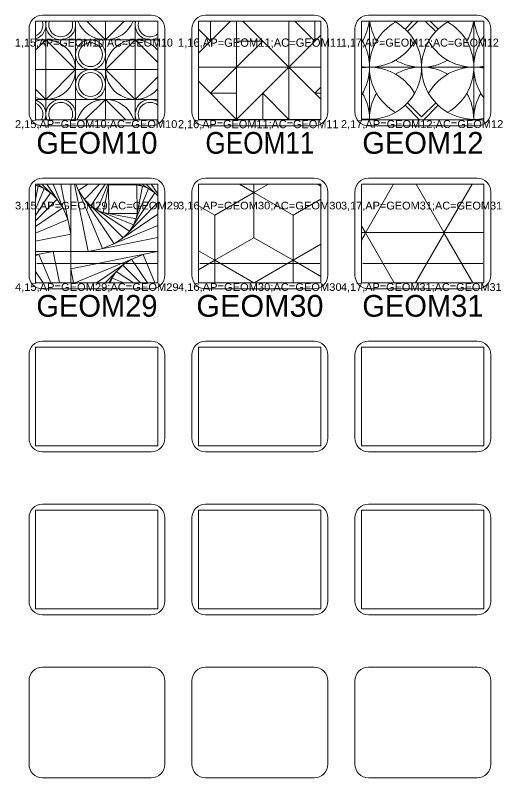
# Model space of a CAD drawing. Extents: x 95935 to 95946.4, y 95971.2 to 95974.7.
# Drawn here: x 95943.435 to 95945.23, y 95971.925 to 95974.732 of the extents above; entities that cross this region are included whole.
import ezdxf
from ezdxf.enums import TextEntityAlignment as Align

# ---------------------------------------------------------------- set-up
doc = ezdxf.new("R2010")
doc.units = 0
doc.header["$LTSCALE"] = 0.032
for name, color, linetype, lineweight in [('1', 7, 'Continuous', 13), ('2', 7, 'Continuous', 13), ('25', 7, 'Continuous', 13), ('6', 7, 'Continuous', 13), ('63', 7, 'Continuous', 13)]:
    doc.layers.add(name, color=color, linetype=linetype, lineweight=lineweight)
doc.layers.add('20', color=7, linetype='Continuous')

msp = doc.modelspace()

# ---------------------------------------------------------------- linework, layer by layer
at = {"layer": '1'}
for p, q in [((95943.5357, 95974.7318), (95943.9357, 95974.7318)), ((95944.1357, 95974.7318), (95944.5357, 95974.7318)), ((95944.7357, 95974.7318), (95945.1357, 95974.7318)), ((95943.4857, 95974.3747), (95943.4857, 95974.6818)), ((95943.9857, 95974.6818), (95943.9857, 95974.3747)), ((95944.0857, 95974.3747), (95944.0857, 95974.6818)), ((95944.5857, 95974.6818), (95944.5857, 95974.3747)), ((95944.6857, 95974.3747), (95944.6857, 95974.6818)), ((95945.1857, 95974.6818), (95945.1857, 95974.3747)), ((95943.9357, 95974.3247), (95943.5357, 95974.3247)), ((95944.5357, 95974.3247), (95944.1357, 95974.3247)), ((95945.1357, 95974.3247), (95944.7357, 95974.3247)), ((95943.5357, 95974.1318), (95943.9357, 95974.1318)), ((95944.1357, 95974.1318), (95944.5357, 95974.1318)), ((95944.7357, 95974.1318), (95945.1357, 95974.1318)), ((95943.4857, 95973.7747), (95943.4857, 95974.0818)), ((95943.9857, 95974.0818), (95943.9857, 95973.7747)), ((95944.0857, 95973.7747), (95944.0857, 95974.0818)), ((95944.5857, 95974.0818), (95944.5857, 95973.7747)), ((95944.6857, 95973.7747), (95944.6857, 95974.0818)), ((95945.1857, 95974.0818), (95945.1857, 95973.7747)), ((95943.9357, 95973.7247), (95943.5357, 95973.7247)), ((95944.5357, 95973.7247), (95944.1357, 95973.7247)), ((95945.1357, 95973.7247), (95944.7357, 95973.7247)), ((95943.5357, 95973.5318), (95943.9357, 95973.5318)), ((95944.1357, 95973.5318), (95944.5357, 95973.5318)), ((95944.7357, 95973.5318), (95945.1357, 95973.5318)), ((95943.4857, 95973.1747), (95943.4857, 95973.4818)), ((95943.9857, 95973.4818), (95943.9857, 95973.1747)), ((95944.0857, 95973.1747), (95944.0857, 95973.4818)), ((95944.5857, 95973.4818), (95944.5857, 95973.1747)), ((95944.6857, 95973.1747), (95944.6857, 95973.4818)), ((95945.1857, 95973.4818), (95945.1857, 95973.1747)), ((95943.9357, 95973.1247), (95943.5357, 95973.1247)), ((95944.5357, 95973.1247), (95944.1357, 95973.1247)), ((95945.1357, 95973.1247), (95944.7357, 95973.1247)), ((95943.5357, 95972.9318), (95943.9357, 95972.9318)), ((95944.1357, 95972.9318), (95944.5357, 95972.9318)), ((95944.7357, 95972.9318), (95945.1357, 95972.9318)), ((95943.4857, 95972.5747), (95943.4857, 95972.8818)), ((95943.9857, 95972.8818), (95943.9857, 95972.5747)), ((95944.0857, 95972.5747), (95944.0857, 95972.8818)), ((95944.5857, 95972.8818), (95944.5857, 95972.5747)), ((95944.6857, 95972.5747), (95944.6857, 95972.8818)), ((95945.1857, 95972.8818), (95945.1857, 95972.5747)), ((95943.9357, 95972.5247), (95943.5357, 95972.5247)), ((95944.5357, 95972.5247), (95944.1357, 95972.5247)), ((95945.1357, 95972.5247), (95944.7357, 95972.5247)), ((95943.5357, 95972.3318), (95943.9357, 95972.3318)), ((95944.1357, 95972.3318), (95944.5357, 95972.3318)), ((95944.7357, 95972.3318), (95945.1357, 95972.3318)), ((95944.7357, 95972.3318), (95945.1357, 95972.3318)), ((95943.4857, 95971.9747), (95943.4857, 95972.2818)), ((95943.9857, 95972.2818), (95943.9857, 95971.9747)), ((95944.0857, 95971.9747), (95944.0857, 95972.2818)), ((95944.5857, 95972.2818), (95944.5857, 95971.9747)), ((95944.6857, 95971.9747), (95944.6857, 95972.2818)), ((95944.6857, 95971.9747), (95944.6857, 95972.2818)), ((95945.1857, 95972.2818), (95945.1857, 95971.9747)), ((95945.1857, 95972.2818), (95945.1857, 95971.9747)), ((95943.9357, 95971.9247), (95943.5357, 95971.9247)), ((95944.5357, 95971.9247), (95944.1357, 95971.9247)), ((95945.1357, 95971.9247), (95944.7357, 95971.9247)), ((95945.1357, 95971.9247), (95944.7357, 95971.9247))]:
    msp.add_line(p, q, dxfattribs=at)
for centre, start, end in [((95943.5357, 95974.6818), 90, 180), ((95943.9357, 95974.6818), 0, 90), ((95944.1357, 95974.6818), 90, 180), ((95944.5357, 95974.6818), 0, 90), ((95944.7357, 95974.6818), 90, 180), ((95945.1357, 95974.6818), 0, 90), ((95943.5357, 95974.3747), 180, 270), ((95943.9357, 95974.3747), 270, 0), ((95944.1357, 95974.3747), 180, 270), ((95944.5357, 95974.3747), 270, 0), ((95944.7357, 95974.3747), 180, 270), ((95945.1357, 95974.3747), 270, 0), ((95943.5357, 95974.0818), 90, 180), ((95943.9357, 95974.0818), 0, 90), ((95944.1357, 95974.0818), 90, 180), ((95944.5357, 95974.0818), 0, 90), ((95944.7357, 95974.0818), 90, 180), ((95945.1357, 95974.0818), 0, 90), ((95943.5357, 95973.7747), 180, 270), ((95943.9357, 95973.7747), 270, 0), ((95944.1357, 95973.7747), 180, 270), ((95944.5357, 95973.7747), 270, 0), ((95944.7357, 95973.7747), 180, 270), ((95945.1357, 95973.7747), 270, 0), ((95943.5357, 95973.4818), 90, 180), ((95943.9357, 95973.4818), 0, 90), ((95944.1357, 95973.4818), 90, 180), ((95944.5357, 95973.4818), 0, 90), ((95944.7357, 95973.4818), 90, 180), ((95945.1357, 95973.4818), 0, 90), ((95943.5357, 95973.1747), 180, 270), ((95943.9357, 95973.1747), 270, 0), ((95944.1357, 95973.1747), 180, 270), ((95944.5357, 95973.1747), 270, 0), ((95944.7357, 95973.1747), 180, 270), ((95945.1357, 95973.1747), 270, 0), ((95943.5357, 95972.8818), 90, 180), ((95943.9357, 95972.8818), 0, 90), ((95944.1357, 95972.8818), 90, 180), ((95944.5357, 95972.8818), 0, 90), ((95944.7357, 95972.8818), 90, 180), ((95945.1357, 95972.8818), 0, 90), ((95943.5357, 95972.5747), 180, 270), ((95943.9357, 95972.5747), 270, 0), ((95944.1357, 95972.5747), 180, 270), ((95944.5357, 95972.5747), 270, 0), ((95944.7357, 95972.5747), 180, 270), ((95945.1357, 95972.5747), 270, 0), ((95943.5357, 95972.2818), 90, 180), ((95943.9357, 95972.2818), 0, 90), ((95944.1357, 95972.2818), 90, 180), ((95944.5357, 95972.2818), 0, 90), ((95944.7357, 95972.2818), 90, 180), ((95944.7357, 95972.2818), 90, 180), ((95945.1357, 95972.2818), 0, 90), ((95945.1357, 95972.2818), 0, 90), ((95943.5357, 95971.9747), 180, 270), ((95943.9357, 95971.9747), 270, 0), ((95944.1357, 95971.9747), 180, 270), ((95944.5357, 95971.9747), 270, 0), ((95944.7357, 95971.9747), 180, 270), ((95944.7357, 95971.9747), 180, 270), ((95945.1357, 95971.9747), 270, 0), ((95945.1357, 95971.9747), 270, 0)]:
    msp.add_arc(centre, 0.05, start, end, dxfattribs=at)
at = {"layer": '2'}
for points in [[(95943.9601, 95974.7099), (95943.5097, 95974.7099), (95943.5097, 95974.3468), (95943.9601, 95974.3468)], [(95944.5601, 95974.7099), (95944.1097, 95974.7099), (95944.1097, 95974.3468), (95944.5601, 95974.3468)], [(95945.1601, 95974.7099), (95944.7097, 95974.7099), (95944.7097, 95974.3468), (95945.1601, 95974.3468)], [(95943.9601, 95974.1099), (95943.5097, 95974.1099), (95943.5097, 95973.7468), (95943.9601, 95973.7468)], [(95944.5601, 95974.1099), (95944.1097, 95974.1099), (95944.1097, 95973.7468), (95944.5601, 95973.7468)], [(95945.1601, 95974.1099), (95944.7097, 95974.1099), (95944.7097, 95973.7468), (95945.1601, 95973.7468)], [(95943.9601, 95973.5099), (95943.5097, 95973.5099), (95943.5097, 95973.1468), (95943.9601, 95973.1468)], [(95944.5601, 95973.5099), (95944.1097, 95973.5099), (95944.1097, 95973.1468), (95944.5601, 95973.1468)], [(95945.1601, 95973.5099), (95944.7097, 95973.5099), (95944.7097, 95973.1468), (95945.1601, 95973.1468)], [(95943.9601, 95972.9099), (95943.5097, 95972.9099), (95943.5097, 95972.5468), (95943.9601, 95972.5468)], [(95944.5601, 95972.9099), (95944.1097, 95972.9099), (95944.1097, 95972.5468), (95944.5601, 95972.5468)], [(95945.1601, 95972.9099), (95944.7097, 95972.9099), (95944.7097, 95972.5468), (95945.1601, 95972.5468)]]:
    msp.add_lwpolyline(points, close=True, dxfattribs=at)
at = {"layer": '25'}
for p, q in [((95943.9569, 95973.8178), (95943.5141, 95973.8178)), ((95944.5569, 95973.8178), (95944.1141, 95973.8178)), ((95945.1569, 95973.8178), (95944.7141, 95973.8178))]:
    msp.add_line(p, q, dxfattribs=at)
at = {"layer": '6'}
for p, q in [((95943.5477, 95974.7099), (95943.5477, 95974.3468)), ((95943.6574, 95974.7099), (95943.6574, 95974.3468)), ((95943.6987, 95974.7099), (95943.7671, 95974.6415)), ((95943.7671, 95974.7099), (95943.7671, 95974.3468)), ((95943.7671, 95974.6415), (95943.8355, 95974.7099)), ((95943.8768, 95974.7099), (95943.8768, 95974.3468)), ((95944.1097, 95974.5922), (95944.2274, 95974.7099)), ((95944.2501, 95974.7099), (95944.2501, 95974.3468)), ((95944.2728, 95974.7099), (95944.5601, 95974.4226)), ((95944.4421, 95974.7099), (95944.4421, 95974.3468)), ((95944.7391, 95974.7099), (95944.7391, 95974.3468)), ((95944.8993, 95974.7099), (95944.8703, 95974.6808)), ((95944.9175, 95974.7099), (95944.8793, 95974.6718)), ((95944.9447, 95974.7099), (95944.9829, 95974.6718)), ((95944.9629, 95974.7099), (95944.9919, 95974.6808)), ((95945.1231, 95974.7099), (95945.1231, 95974.3468)), ((95943.5097, 95974.6415), (95943.9601, 95974.6415)), ((95944.2501, 95974.3486), (95944.5601, 95974.6586)), ((95943.5097, 95974.5318), (95943.9601, 95974.5318)), ((95944.1097, 95974.5406), (95944.5601, 95974.5406)), ((95944.7097, 95974.5406), (95945.1601, 95974.5406)), ((95943.8768, 95974.4221), (95943.9601, 95974.5054)), ((95944.1097, 95974.489), (95944.2501, 95974.3486)), ((95943.5097, 95974.4601), (95943.5477, 95974.4221)), ((95943.5097, 95974.4221), (95943.9601, 95974.4221)), ((95944.922, 95974.3486), (95944.8703, 95974.4004)), ((95944.9311, 95974.3577), (95944.8793, 95974.4094)), ((95944.9311, 95974.3577), (95944.9829, 95974.4094)), ((95944.9402, 95974.3486), (95944.9919, 95974.4004)), ((95944.1097, 95974.3486), (95944.5601, 95974.3486)), ((95944.1541, 95974.3468), (95944.1541, 95974.3486)), ((95944.2483, 95974.3468), (95944.2501, 95974.3486)), ((95944.2501, 95974.3486), (95944.2519, 95974.3468)), ((95944.4421, 95974.3486), (95944.4439, 95974.3468)), ((95944.5381, 95974.3468), (95944.5381, 95974.3486)), ((95944.922, 95974.3486), (95944.9202, 95974.3468)), ((95944.9402, 95974.3486), (95944.942, 95974.3468)), ((95943.6392, 95974.1099), (95943.6392, 95973.7468)), ((95943.6537, 95974.1099), (95943.7032, 95973.8623)), ((95943.6579, 95974.1099), (95943.7565, 95973.873)), ((95943.7027, 95974.1099), (95943.6676, 95974.0863)), ((95943.7453, 95974.1099), (95943.6896, 95974.0537)), ((95943.7659, 95974.1099), (95943.7133, 95974.0302)), ((95943.7758, 95974.1099), (95943.7369, 95974.0146)), ((95943.7793, 95974.1099), (95943.7593, 95974.0055)), ((95943.9031, 95974.1031), (95943.8676, 95974.1099)), ((95943.9254, 95974.094), (95943.8863, 95974.1099)), ((95943.9491, 95974.0784), (95943.9014, 95974.1099)), ((95943.9601, 95974.0675), (95943.9173, 95974.1099)), ((95943.9601, 95974.0739), (95943.9359, 95974.1099)), ((95943.9601, 95974.1053), (95943.9582, 95974.1099)), ((95944.2603, 95974.1099), (95944.3138, 95974.079)), ((95944.3138, 95974.079), (95944.3138, 95974.1099)), ((95944.3673, 95974.1099), (95944.3138, 95974.079)), ((95944.5483, 95974.1099), (95944.5601, 95974.1031)), ((95944.7239, 95973.9303), (95944.8276, 95974.1099)), ((95944.9108, 95974.1099), (95945.0127, 95973.9333)), ((95945.0132, 95973.9303), (95945.1169, 95974.1099)), ((95943.6676, 95974.0863), (95943.7992, 95973.8907)), ((95943.8553, 95973.9364), (95943.9491, 95974.0784)), ((95943.8709, 95973.96), (95943.9254, 95974.094)), ((95943.88, 95973.9824), (95943.9031, 95974.1031)), ((95944.1698, 95973.9959), (95944.3138, 95974.079)), ((95944.3138, 95974.079), (95944.3138, 95973.9127)), ((95944.4578, 95973.9959), (95944.3138, 95974.079)), ((95943.6896, 95974.0537), (95943.8318, 95973.9127)), ((95944.4578, 95973.9959), (95944.5601, 95974.0549)), ((95943.7133, 95974.0302), (95943.8553, 95973.9364)), ((95943.8318, 95973.9127), (95943.9601, 95974.0421)), ((95944.1698, 95973.9959), (95944.1097, 95974.0306)), ((95943.7369, 95974.0146), (95943.8709, 95973.96)), ((95943.7593, 95974.0055), (95943.88, 95973.9824)), ((95943.7992, 95973.8907), (95943.9601, 95973.999)), ((95944.1698, 95973.9959), (95944.1698, 95973.8296)), ((95944.4578, 95973.9959), (95944.4578, 95973.8296)), ((95943.7565, 95973.873), (95943.9601, 95973.9578)), ((95944.7097, 95973.957), (95944.7234, 95973.9333)), ((95943.7032, 95973.8623), (95943.9601, 95973.9137)), ((95944.1698, 95973.8296), (95944.3138, 95973.9127)), ((95944.4578, 95973.8296), (95944.3138, 95973.9127)), ((95944.7097, 95973.9325), (95944.7239, 95973.9325)), ((95944.7097, 95973.9035), (95944.7234, 95973.9272)), ((95944.7239, 95973.9303), (95944.8298, 95973.7468)), ((95944.7252, 95973.9325), (95945.0132, 95973.9325)), ((95944.9085, 95973.7468), (95945.0127, 95973.9272)), ((95945.0132, 95973.9303), (95945.1191, 95973.7468)), ((95945.0145, 95973.9325), (95945.1601, 95973.9325)), ((95944.4578, 95973.8296), (95944.5601, 95973.8886)), ((95943.5097, 95973.8623), (95943.9601, 95973.8623)), ((95943.9592, 95973.8623), (95943.6392, 95973.7983)), ((95943.9601, 95973.8578), (95943.9592, 95973.8623)), ((95944.1698, 95973.8296), (95944.1097, 95973.7949)), ((95944.1698, 95973.8296), (95944.3133, 95973.7468)), ((95944.4578, 95973.8296), (95944.3143, 95973.7468)), ((95944.4578, 95973.7468), (95944.4578, 95973.8296)), ((95944.4578, 95973.8296), (95944.5601, 95973.7706)), ((95943.6392, 95973.7983), (95943.6495, 95973.7468)), ((95943.5378, 95973.7468), (95943.5097, 95973.7886)), ((95943.5122, 95973.7468), (95943.5097, 95973.7493))]:
    msp.add_line(p, q, dxfattribs=at)
for points in [[(95944.1097, 95974.681), (95944.1541, 95974.6366), (95944.1541, 95974.7099)], [(95944.4648, 95974.7099), (95944.5381, 95974.6366), (95944.5381, 95974.7099)], [(95943.5477, 95974.4221), (95943.6574, 95974.5318), (95943.5477, 95974.6415), (95943.5097, 95974.6035)], [(95943.9601, 95974.5582), (95943.8768, 95974.6415), (95943.7671, 95974.5318), (95943.8768, 95974.4221)], [(95944.2501, 95974.5406), (95944.3461, 95974.6366), (95944.2501, 95974.6366)], [(95944.2501, 95974.5406), (95944.1541, 95974.4446), (95944.2501, 95974.4446)], [(95944.4421, 95974.3486), (95944.3461, 95974.4446), (95944.3461, 95974.3486)], [(95944.5601, 95974.4666), (95944.5381, 95974.4446), (95944.5601, 95974.4446)], [(95943.8424, 95974.3468), (95943.7671, 95974.4221), (95943.6918, 95974.3468)], [(95943.5097, 95973.9004), (95943.6392, 95973.9263), (95943.6025, 95974.1099)], [(95943.5097, 95973.9301), (95943.6285, 95973.9796), (95943.5742, 95974.1099)], [(95943.5097, 95973.9543), (95943.6108, 95974.0223), (95943.5519, 95974.1099)], [(95943.5097, 95973.9751), (95943.5888, 95974.0549), (95943.5333, 95974.1099)], [(95943.5097, 95973.9945), (95943.5651, 95974.0784), (95943.5174, 95974.1099)], [(95943.5097, 95974.0161), (95943.5414, 95974.094), (95943.5097, 95974.1069)], [(95943.5097, 95974.054), (95943.5191, 95974.1031), (95943.5097, 95974.1049)], [(95943.5983, 95973.7468), (95943.5752, 95973.8623), (95943.5097, 95973.8492)], [(95943.5655, 95973.7468), (95943.5219, 95973.8516), (95943.5097, 95973.8465)], [(95943.9495, 95973.7468), (95943.9059, 95973.8516), (95943.6542, 95973.7468)], [(95944.1698, 95973.7468), (95944.1698, 95973.8296), (95944.1097, 95973.8643)], [(95943.9218, 95973.7468), (95943.8632, 95973.8339), (95943.7337, 95973.7468)], [(95943.8963, 95973.7468), (95943.8306, 95973.8119), (95943.766, 95973.7468)], [(95943.8698, 95973.7468), (95943.8071, 95973.7882), (95943.7798, 95973.7468)], [(95943.835, 95973.7468), (95943.7915, 95973.7645), (95943.7843, 95973.7468)]]:
    msp.add_lwpolyline(points, dxfattribs=at)
msp.add_lwpolyline([(95943.8839, 95974.0025), (95943.883, 95974.107), (95943.7785, 95974.1061), (95943.7794, 95974.0016)], close=True, dxfattribs=at)
for centre, radius in [((95943.7123, 95974.5867), 0.0549), ((95943.7123, 95974.5867), 0.0439), ((95943.7123, 95974.477), 0.0549), ((95943.7123, 95974.477), 0.0439)]:
    msp.add_circle(centre, radius, dxfattribs=at)
for centre, radius, start, end in [((95943.4928, 95974.6964), 0.0549, 287.9118, 14.2619), ((95943.4928, 95974.6964), 0.0439, 292.609, 17.9353), ((95943.6025, 95974.6964), 0.0549, 165.7381, 14.2619), ((95943.6025, 95974.6964), 0.0439, 162.0647, 17.9353), ((95943.7671, 95974.7512), 0.1097, 202.137, 337.863), ((95943.9317, 95974.6964), 0.0549, 165.7381, 301.1961), ((95943.9317, 95974.6964), 0.0439, 162.0647, 310.3504), ((95944.7391, 95974.5406), 0.192, 261.1919, 61.8567), ((95944.5471, 95974.7326), 0.192, 330.0929, 353.2101), ((95944.9311, 95974.5406), 0.192, 120.0536, 239.9928), ((95944.9311, 95974.7326), 0.192, 186.7899, 209.9071), ((95945.1231, 95974.5406), 0.192, 118.1433, 281.1109), ((95944.9311, 95974.5406), 0.192, 300.0536, 59.9928), ((95944.9311, 95974.7326), 0.192, 330.0929, 353.2101), ((95945.3151, 95974.7326), 0.192, 186.7899, 209.9071), ((95943.5477, 95974.5318), 0.1097, 249.7435, 110.2565), ((95943.8768, 95974.5318), 0.1097, 40.6253, 319.3747), ((95944.5471, 95974.5406), 0.192, 327.8734, 32.1266), ((95945.3151, 95974.5406), 0.192, 143.8322, 216.1678), ((95944.7391, 95974.7326), 0.192, 261.1919, 329.9928), ((95945.1231, 95974.7326), 0.192, 210.0536, 281.1109), ((95944.9311, 95974.7326), 0.192, 240.0929, 269.7725), ((95944.9311, 95974.7326), 0.192, 270.2275, 299.9071), ((95944.7391, 95974.3486), 0.192, 30.0536, 98.8081), ((95944.9311, 95974.3486), 0.192, 90.2275, 119.9071), ((95944.9311, 95974.3486), 0.192, 60.0929, 89.7725), ((95945.1231, 95974.3486), 0.192, 78.8891, 149.9928), ((95944.5471, 95974.3486), 0.192, 0.2275, 29.9071), ((95944.9311, 95974.3486), 0.192, 150.0929, 179.7725), ((95944.9311, 95974.3486), 0.192, 0.2275, 29.9071), ((95945.3151, 95974.3486), 0.192, 150.0929, 179.7725), ((95943.4928, 95974.3672), 0.0549, 338.1192, 72.0882), ((95943.6025, 95974.3672), 0.0549, 338.1192, 201.8808), ((95943.7671, 95974.3124), 0.1097, 18.28, 161.72), ((95943.9317, 95974.3672), 0.0549, 58.8039, 201.8808), ((95943.4928, 95974.3672), 0.0439, 332.235, 67.391), ((95943.6025, 95974.3672), 0.0439, 332.235, 207.765), ((95943.9317, 95974.3672), 0.0439, 49.6496, 207.765), ((95944.7391, 95974.1566), 0.192, 82.1483, 97.8517), ((95944.9311, 95974.3486), 0.192, 180.2275, 180.5372), ((95944.5471, 95974.3486), 0.192, 359.4628, 359.7725), ((95945.1231, 95974.1566), 0.192, 82.1483, 97.8517), ((95945.3151, 95974.3486), 0.192, 180.2275, 180.5372), ((95944.9311, 95974.3486), 0.192, 359.4628, 359.7725)]:
    msp.add_arc(centre, radius, start, end, dxfattribs=at)

# ---------------------------------------------------------------- texts
at = {"layer": '20'}
for s, p in [('GEOM10', (95943.7358, 95974.222)), ('GEOM12', (95944.9358, 95974.222)), ('GEOM29', (95943.7358, 95973.622)), ('GEOM31', (95944.9358, 95973.622))]:
    msp.add_text(s, height=0.08, dxfattribs=at).set_placement(p, align=Align.CENTER)
for s, width, p in [('GEOM11', 0.9, (95944.3358, 95974.222)), ('GEOM30', 1.05, (95944.3357, 95973.622))]:
    msp.add_text(s, height=0.08, dxfattribs=dict(at, width=width)).set_placement(p, align=Align.CENTER)
at = {"layer": '63'}
for s, height, p in [('1,15,AP=GEOM10;AC=GEOM10', 0.0295, (95943.4341, 95974.6163)), ('1,16,AP=GEOM11;AC=GEOM11', 0.0307, (95944.0341, 95974.6157)), ('1,17,AP=GEOM12;AC=GEOM12', 0.0295, (95944.6341, 95974.6163)), ('2,16,AP=GEOM11;AC=GEOM11', 0.03, (95944.0341, 95974.3161))]:
    msp.add_text(s, height=height, dxfattribs=at).set_placement(p)
for s, height, width, p in [('2,15,AP=GEOM10;AC=GEOM10', 0.0289, 1.05, (95943.4341, 95974.3166)), ('2,17,AP=GEOM12;AC=GEOM12', 0.0289, 1.05, (95944.6341, 95974.3166)), ('3,15,AP=GEOM29;AC=GEOM29', 0.0279, 1.1, (95943.4341, 95974.0171)), ('3,16,AP=GEOM30;AC=GEOM30', 0.0278, 1.1, (95944.0341, 95974.0172)), ('3,17,AP=GEOM31;AC=GEOM31', 0.0287, 1.05, (95944.6341, 95974.0167)), ('4,15,AP=GEOM29;AC=GEOM29', 0.0278, 1.1, (95943.4341, 95973.7172)), ('4,16,AP=GEOM30;AC=GEOM30', 0.0278, 1.1, (95944.0341, 95973.7172)), ('4,17,AP=GEOM31;AC=GEOM31', 0.0286, 1.05, (95944.6341, 95973.7168))]:
    msp.add_text(s, height=height, dxfattribs=dict(at, width=width)).set_placement(p)

doc.saveas('drawing.dxf')
